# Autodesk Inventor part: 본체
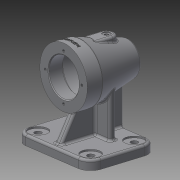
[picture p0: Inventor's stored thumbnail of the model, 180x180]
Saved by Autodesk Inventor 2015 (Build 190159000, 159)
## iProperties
Created: 2024-12
Part Number: 본체
Material: 알루미늄 6061
Document SubType Name: Modeling
Designer: 102566
Density: 2.7 g/cm^3
Appearance: 기본값
Mass: 753.502 g
Surface Area: 670.934 cm^2
Volume: 279.075 cm^3
Author: 102566
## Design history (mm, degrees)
sketch "스케치1"
  geometry: L1 (57, 44.5)-(-57, 44.5); L2 (-57, 44.5)-(-57, -44.5); L3 (-57, -44.5)-(57, -44.5); L4 (57, -44.5)-(57, 44.5); L5 (57, 44.5)-(-57, -44.5); L6 (-57, 44.5)-(57, -44.5); 1 further point
  constraints: 12 end point, 2 midpoint, 2 parallel, 1 horizontal, 1 perpendicular
  dimensions: "d0" = 114 distance of L2.end L3.end; "d1" = 89 distance of L3.end L1.start
extrude "돌출1" new body sketch "스케치1" distance "d2" = 12; taper "d3" = 0 deg
sketch "스케치3"
  geometry: L1 (82, 35.374)-(82, -61.09); L2 (82, 29.5)-(119, 29.5); L3 (119, 29.5)-(119, 9.5); L4 (0, 44.5)-(0, -44.5) reference; L5 (0, 44.5)-(12, 44.5) reference; L6 (119, 9.5)-(103, -54.5); L7 (103, -54.5)-(82, -54.5); 1 further point
  constraints: 10 end point, 2 perpendicular, 2 point on line, 1 horizontal, 1 vertical
  dimensions: "d7" = 119 distance between parallel lines of L4 L3; "d8" = 15 distance between parallel lines of L5 L2; "d11" = 20 distance of L2.end L3.end; "d12" = 84 distance between parallel lines of L7 L2; "d13" = 74 diameter of L3 L1; "d15" = 21 distance of L6.end L7.end
revolve "회전1" sketch "스케치3" stored, may be unused: angle "d16" = 90 deg
sketch "스케치4"
  geometry: L1 (57, 44.5)-(-57, 44.5) reference; L2 (-28, 15.5)-(28, 15.5); L3 (28, 15.5)-(28, 7.5); L4 (28, 7.5)-(-28, 7.5); L5 (-28, 7.5)-(-28, 15.5); 1 further point
  constraints: 8 end point, 2 parallel, 1 horizontal, 1 perpendicular
  dimensions: "d17" = 29 distance between parallel lines of L1 L2; "d18" = 8 distance of L4.end L2.start; "d19" = 56 distance of L2.start L2.end; "d20" = 28 distance from line of point (0, 0) L3
extrude "돌출2" join sketch "스케치4" stored distance "d21" = 18; taper "d22" = 0 deg
sketch "스케치5"
  geometry: L1 (57, 44.5)-(-57, 44.5) reference; L2 (-5, 44.5)-(5, 44.5); L3 (5, 44.5)-(5, 11.5); L4 (5, 11.5)-(-5, 11.5); L5 (-5, 11.5)-(-5, 44.5); 1 further point
  constraints: 8 end point, 2 parallel, 1 horizontal, 1 perpendicular, 1 point on line
  dimensions: "d23" = 10 distance of L3.end L4.end; "d24" = 5 distance from line of point (0, 0) L3; "d25" = 33 distance of L2.end L3.end
extrude "돌출3" join sketch "스케치5" stored distance "d26" = 18; taper "d27" = 0 deg
node "작업 평면2"
sketch "스케치6"
  geometry: L1 (7, 12)-(33.995, 58.757); L2 (33.995, 58.757)-(62.56, 58.757); L3 (62.56, 58.757)-(62.56, 12); L4 (7, 12)-(62.56, 12); L5 (89, 12)-(0, 12) reference; L6 (0, 0)-(0, 12) reference; L7 (89, 0)-(0, 0) reference; 1 further point
  constraints: 8 end point, 1 collinear, 1 horizontal, 1 perpendicular
  dimensions: "d29" = 7 distance from line of L6 L1.start; "d30" = 60 deg angle of L4 L1; "d31" = 28.56483 distance of L1.end L2.end; "d32" = 46.75708 distance of L2.end L3.end; "d33" = 12 distance between parallel lines of L7 L4
extrude "돌출4" join sketch "스케치6" stored distance "d34" = 10; taper "d35" = 0 deg
sketch "스케치7"
  geometry: L1 (15, 82)-(99, 82); L2 (15, 82)-(15, 105.5); L3 (33, 105.5)-(33, 107.489); L4 (39.29, 112.32)-(78, 101.981); L5 (78, 101.981)-(78, 99.5); L6 (78, 99.5)-(88, 99.5); L7 (88, 99.5)-(88, 97.5); L8 (88, 97.5)-(91, 97.5); L9 (91, 97.5)-(91, 82); L10 (33, 105.5)-(15, 105.5); L11 (89, 0)-(0, 0) reference; L12 (99, 61)-(99, 103) reference; A1 r 5 centre (38, 107.489) between (39.29, 112.32) and (33, 107.489); 2 further points
  constraints: 20 end point, 5 perpendicular, 3 point on line, 2 point on circle, 2 tangent, 1 centre point, 1 parallel, 1 vertical
  dimensions: "d36" = 47 diameter of L10 L1; "d37" = 45 distance between parallel lines of L5 L3; "d38" = 18 distance of L3.start L2.end; "d39" = 10 distance of L5.end L6.end; "d40" = 3 distance of L7.end L8.end; "d41" = 35 diameter of L6 L1; "d42" = 31 diameter of L8 L1; "d43" = 64 diameter of point (33, 114) L1; "d45" = 82 distance between parallel lines of L11 L1; "d99" = 5 radius of A1; "d100" = 90 deg angle of L10 L2; "d101" = 8 distance between parallel lines of L12 L9; "d102" = 104.954 deg angle of L5 L4
revolve "회전2" sketch "스케치7" stored, may be unused: angle "d46" = 90 deg
sketch "스케치8"
  geometry: L1 (-57, 44.5)-(-57, -44.5) reference; L2 (-57, -44.5)-(57, -44.5) reference; 2 further points
  dimensions: "d47" = 16 distance from line of L2 point (-41, -28.5); "d48" = 16 distance from line of L1 point (-41, -28.5)
hole "구멍1" sketch "스케치8" at (-41, -28.5) diameter "d49" = 9; stored, may be unused: countersink angle "d53" = 90 deg, drill point angle "d55" = 0 deg; dims "d50" = 6, "d51" = 24, "d52" = 2, "d54" = 8
sketch "스케치9" dims "d62" = 57
  geometry: C1 r 23.5 at (0, 0) reference; C2 r 37 at (0, 0) reference; 3 further points
  constraints: 2 vertical alignment, 1 coincident, 2 other
hole "구멍2" sketch "스케치9" at (0, 28.5) diameter "d63" = 3.242; stored, may be unused: countersink angle "d67" = 90 deg, drill point angle "d69" = 118 deg; dims "d64" = 8, "d65" = 24, "d66" = 2, "d68" = 11.8
node "작업 평면3"
sketch "스케치10"
  geometry: L1 (-10, 3.5)-(10, 3.5); L2 (10, 3.5)-(10, -36.5); L3 (10, -36.5)-(-10, -36.5); L4 (-10, -36.5)-(-10, 3.5); L5 (-37, 29.5)-(37, 29.5) reference; 1 further point
  constraints: 8 end point, 2 parallel, 1 horizontal, 1 perpendicular
  dimensions: "d74" = 20 distance of L2.end L3.end; "d75" = 66 distance between parallel lines of L5 L3; "d76" = 10 distance from line of point (0, 0) L2; "d77" = 40 distance of L1.end L2.end
extrude "돌출5" join sketch "스케치10" stored distance "d78" = 10; taper "d79" = 0 deg
fillet "모깎기1" dims "d80" = 16
fillet "모깎기2" dims "d81" = 3
fillet "모깎기3" dims "d82" = 3
fillet "모깎기4" dims "d83" = 3
sketch "스케치11"
  geometry: L1 (37, -29.5)-(-37, -29.5) reference; 2 further points
  dimensions: "d84" = 56 distance from line of L1 point (0, 26.5)
hole "구멍3" sketch "스케치11" at (0, 26.5) diameter "d85" = 4.917; stored, may be unused: countersink angle "d89" = 90 deg, drill point angle "d91" = 118 deg; dims "d86" = 12, "d87" = 10, "d88" = 1, "d90" = 17.55
fillet "모깎기5" dims "d92" = 10
fillet "모깎기6" dims "d93" = 3
node "작업 평면5"
sketch "스케치13"
  geometry: 3 further points
  constraints: 1 vertical alignment, 1 other
feature "엠보싱1" sketch "스케치13" dims "d0" = 114, "d1" = 89, "d96" = 0.5, "d97" = 0
fillet "모깎기7" dims "d98" = 0.3
fillet "모깎기8" dims "d103" = 3
chamfer "모따기1" distance "d104" = 1; stored, may be unused: second distance "d105" = 2, angle "d106" = 45 deg
fillet "모깎기9" dims "d107" = 3
fillet "모깎기10" dims "d108" = 3
fillet "모깎기11" dims "d109" = 3
node "솔리드1"
pattern_linear "직사각형 패턴1" dims "d58" = 57, "d61" = 82
pattern_circular "원형 패턴1" dims angle "d71" = 360 deg
other parameters: "d28" = -57, "d73" = -115
